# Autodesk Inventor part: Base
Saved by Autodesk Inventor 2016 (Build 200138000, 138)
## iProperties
Created: 2013-08
Part Number: Base
Material: Générique
Document SubType Name: Modeling
Designer: hilarion
Density: 1 g/cm^3
Appearance: Par défaut
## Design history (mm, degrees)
node "Base2"
node "Base"
node "Base1"
